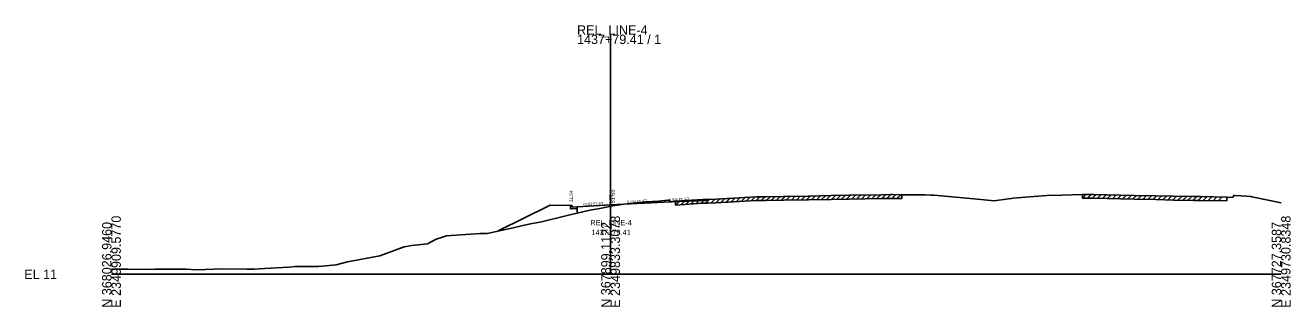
# Model space of a CAD drawing. Extents: x -26 to 2350146, y -10 to 368200.
# Drawn here: x 974.3 to 1351.7, y 9490.3 to 9574.3 of the extents above; entities that cross this region are included whole.
import ezdxf

# ---------------------------------------------------------------- set-up
doc = ezdxf.new("R2010")
doc.units = 0
for name, color, linetype in [('RD_GPK_XS_Cell', 7, 'Continuous'), ('RD_XS_CurbBase', 7, 'Continuous'), ('RD_XS_CurbFront', 7, 'Continuous'), ('RD_XS_CurbTop', 7, 'Continuous'), ('RD_XS_EarthShd', 7, 'Continuous'), ('RD_XS_ExGround', 7, 'Continuous'), ('RD_XS_ExPaveRet', 7, 'Continuous'), ('RD_XS_MatchLine', 7, 'Continuous'), ('RD_XS_Pave', 7, 'Continuous'), ('RD_XS_PaveShd', 7, 'Continuous'), ('RD_XS_TieSlope', 7, 'Continuous'), ('RD_XS_TX_Elev_EX', 7, 'Continuous'), ('RD_XS_TX_Elev_PR', 7, 'Continuous'), ('RD_XS_TX_Slope', 7, 'Continuous'), ('RD_XS_TX_Station', 7, 'Continuous'), ('RD_XS_TX_TOC', 7, 'Continuous')]:
    doc.layers.add(name, color=color, linetype=linetype)

msp = doc.modelspace()

# ---------------------------------------------------------------- linework, layer by layer
at = {"layer": 'RD_GPK_XS_Cell'}
for p, q in [((1148.86, 9500), (1148.86, 9571.52)), ((1000, 9500), (1148.86, 9500)), ((1148.86, 9500), (1348.86, 9500))]:
    msp.add_line(p, q, dxfattribs=at)
at = {"layer": 'RD_XS_CurbBase'}
for p, q in [((1136.86, 9520.54), (1136.86, 9519.54)), ((1136.86, 9519.54), (1137.36, 9519.54)), ((1137.36, 9519.54), (1138.86, 9519.63)), ((1138.86, 9518.56), (1138.86, 9519.63))]:
    msp.add_line(p, q, dxfattribs=at)
at = {"layer": 'RD_XS_CurbFront'}
msp.add_line((1138.86, 9519.63), (1138.86, 9520.13), dxfattribs=at)
at = {"layer": 'RD_XS_CurbTop'}
for p, q in [((1137.36, 9520.54), (1136.86, 9520.54)), ((1137.44, 9520.04), (1137.36, 9520.54)), ((1138.86, 9520.13), (1137.44, 9520.04)), ((1138.86, 9520.15), (1138.86, 9520.13))]:
    msp.add_line(p, q, dxfattribs=at)
at = {"layer": 'RD_XS_EarthShd'}
for p, q in [((1171.88, 9521.82), (1177.88, 9522.06)), ((1136.86, 9520.54), (1130.86, 9520.66))]:
    msp.add_line(p, q, dxfattribs=at)
at = {"layer": 'RD_XS_ExGround'}
msp.add_lwpolyline([(1000, 9501.5), (1001.98, 9501.5), (1002.89, 9501.49), (1004.88, 9501.51), (1012.04, 9501.38), (1013.08, 9501.54), (1019.03, 9501.48), (1022.35, 9501.51), (1025.24, 9501.34), (1030.62, 9501.49), (1033.35, 9501.62), (1040.41, 9501.56), (1041.83, 9501.53), (1042.57, 9501.53), (1044.04, 9501.57), (1049.19, 9501.89), (1053, 9502.11), (1054.76, 9502.29), (1057.27, 9502.31), (1061.75, 9502.36), (1067.05, 9502.85), (1070.35, 9503.69), (1080.07, 9505.46), (1087.28, 9508.18), (1089.56, 9508.63), (1094.22, 9509.08), (1096.82, 9510.48), (1098.73, 9511.04), (1099.9, 9511.47), (1109.98, 9512.19), (1112.01, 9512.18), (1119.76, 9513.88), (1122.31, 9514.5), (1124.5, 9514.91), (1128.24, 9515.68), (1135.49, 9517.43), (1136.28, 9517.61), (1143.21, 9519.21), (1145.11, 9519.57), (1148.53, 9520.23), (1148.86, 9520.28), (1152.83, 9520.91), (1159.51, 9521.6), (1163.2, 9521.86), (1165.96, 9522.09), (1166.48, 9522.1), (1166.66, 9521.61), (1167.13, 9521.64), (1168.27, 9521.77), (1176.3, 9522.33), (1176.74, 9522.35), (1177.55, 9522.39), (1177.83, 9522.32), (1180.24, 9522.43), (1183.61, 9522.61), (1183.94, 9522.66), (1188.82, 9522.94), (1192.23, 9523.15), (1193.4, 9523.16), (1195.19, 9523.13), (1200.41, 9523.24), (1207.85, 9523.34), (1214.69, 9523.47), (1219.99, 9523.58), (1229.64, 9523.75), (1232.49, 9523.8), (1232.99, 9523.79), (1235.77, 9523.75), (1242.7, 9523.67), (1244.39, 9523.61), (1245.4, 9523.59), (1246.48, 9523.53), (1257.17, 9522.54), (1261.28, 9522.11), (1263.31, 9521.94), (1267.54, 9522.51), (1268.4, 9522.63), (1268.82, 9522.67), (1270.14, 9522.79), (1279, 9523.5), (1283.46, 9523.6), (1286.51, 9523.66), (1289.56, 9523.82), (1292.85, 9523.84), (1305.01, 9523.55), (1311.46, 9523.41), (1316.78, 9523.29), (1322.72, 9523.2), (1324.18, 9523.18), (1324.75, 9523.17), (1332.64, 9523.03), (1332.84, 9522.96), (1334.54, 9522.98), (1334.73, 9523.48), (1335.13, 9523.48), (1338.51, 9523.28), (1339.77, 9523.2), (1340.11, 9523.15), (1340.59, 9523.04), (1348.86, 9521.34)], dxfattribs=at)
at = {"layer": 'RD_XS_ExPaveRet'}
for p, q in [((1168.27, 9520.63), (1169.5, 9521.85)), ((1168.27, 9520.63), (1168.27, 9521.77)), ((1169.77, 9520.73), (1171, 9521.96)), ((1171.27, 9520.83), (1172.5, 9522.06)), ((1172.77, 9520.94), (1174, 9522.17)), ((1174.27, 9521.04), (1175.5, 9522.27)), ((1175.77, 9521.15), (1176.98, 9522.36)), ((1177.27, 9521.23), (1178.38, 9522.35)), ((1178.77, 9521.22), (1179.96, 9522.42)), ((1180.27, 9521.29), (1181.48, 9522.5)), ((1181.77, 9521.37), (1182.98, 9522.58)), ((1183.27, 9521.45), (1184.51, 9522.69)), ((1183.94, 9521.52), (1188.82, 9521.8)), ((1184.77, 9521.56), (1185.98, 9522.78)), ((1186.27, 9521.65), (1187.48, 9522.87)), ((1187.77, 9521.74), (1188.98, 9522.95)), ((1188.82, 9521.8), (1192.23, 9522.01)), ((1189.27, 9521.83), (1190.48, 9523.05)), ((1190.77, 9521.92), (1191.98, 9523.14)), ((1192.23, 9522.01), (1193.4, 9522.02)), ((1192.27, 9522.01), (1193.42, 9523.16)), ((1193.4, 9522.02), (1195.19, 9521.99)), ((1193.77, 9522.01), (1194.89, 9523.13)), ((1195.19, 9521.99), (1200.41, 9522.1)), ((1195.27, 9521.99), (1196.43, 9523.16)), ((1196.77, 9522.02), (1197.93, 9523.19)), ((1198.27, 9522.05), (1199.43, 9523.22)), ((1199.77, 9522.08), (1200.93, 9523.25)), ((1200.41, 9522.1), (1207.85, 9522.19)), ((1201.27, 9522.11), (1202.43, 9523.27)), ((1202.77, 9522.13), (1203.93, 9523.29)), ((1204.27, 9522.15), (1205.43, 9523.3)), ((1205.77, 9522.17), (1206.93, 9523.32)), ((1207.27, 9522.19), (1208.43, 9523.35)), ((1207.85, 9522.19), (1214.69, 9522.33)), ((1208.77, 9522.21), (1209.93, 9523.38)), ((1210.27, 9522.24), (1211.43, 9523.41)), ((1211.77, 9522.27), (1212.93, 9523.44)), ((1213.27, 9522.3), (1214.43, 9523.47)), ((1214.69, 9522.33), (1219.99, 9522.44)), ((1214.77, 9522.33), (1215.93, 9523.5)), ((1216.27, 9522.36), (1217.43, 9523.53)), ((1217.77, 9522.39), (1218.93, 9523.56)), ((1219.27, 9522.42), (1220.43, 9523.59)), ((1219.99, 9522.44), (1229.64, 9522.61)), ((1220.77, 9522.45), (1221.93, 9523.61)), ((1222.27, 9522.48), (1223.43, 9523.64)), ((1223.77, 9522.5), (1224.93, 9523.67)), ((1225.27, 9522.53), (1226.43, 9523.7)), ((1226.77, 9522.56), (1227.93, 9523.72)), ((1228.27, 9522.59), (1229.43, 9523.75)), ((1229.64, 9522.61), (1232.49, 9522.66)), ((1229.77, 9522.61), (1230.93, 9523.78)), ((1231.27, 9522.64), (1232.43, 9523.8)), ((1232.49, 9522.66), (1232.99, 9522.65)), ((1232.77, 9522.66), (1233.89, 9523.78)), ((1232.99, 9522.65), (1235.77, 9522.6)), ((1234.27, 9522.63), (1235.39, 9523.75)), ((1235.77, 9523.75), (1235.77, 9522.6)), ((1289.56, 9522.67), (1290.71, 9523.83)), ((1289.56, 9522.67), (1289.56, 9523.82)), ((1289.56, 9522.67), (1292.85, 9522.7)), ((1291.06, 9522.68), (1292.21, 9523.84)), ((1292.56, 9522.7), (1293.69, 9523.82)), ((1292.85, 9522.7), (1305.01, 9522.41)), ((1294.06, 9522.67), (1295.18, 9523.79)), ((1295.56, 9522.63), (1296.68, 9523.75)), ((1297.06, 9522.6), (1298.18, 9523.71)), ((1298.56, 9522.56), (1299.68, 9523.68)), ((1300.06, 9522.53), (1301.18, 9523.64)), ((1301.56, 9522.49), (1302.68, 9523.61)), ((1303.06, 9522.46), (1304.18, 9523.57)), ((1304.56, 9522.42), (1305.68, 9523.54)), ((1305.01, 9522.41), (1311.46, 9522.27)), ((1306.06, 9522.39), (1307.18, 9523.5)), ((1307.56, 9522.35), (1308.68, 9523.47)), ((1309.06, 9522.32), (1310.18, 9523.44)), ((1310.56, 9522.29), (1311.68, 9523.4)), ((1311.46, 9522.27), (1316.78, 9522.15)), ((1312.06, 9522.25), (1313.18, 9523.37)), ((1313.56, 9522.22), (1314.68, 9523.34)), ((1315.06, 9522.18), (1316.18, 9523.3)), ((1316.56, 9522.15), (1317.68, 9523.27)), ((1316.78, 9522.15), (1322.72, 9522.06)), ((1318.06, 9522.13), (1319.19, 9523.25)), ((1319.56, 9522.1), (1320.69, 9523.23)), ((1321.06, 9522.08), (1322.19, 9523.21)), ((1322.56, 9522.06), (1323.69, 9523.18)), ((1322.72, 9522.06), (1324.18, 9522.03)), ((1324.06, 9522.03), (1325.18, 9523.16)), ((1324.18, 9522.03), (1324.75, 9522.02)), ((1324.75, 9522.02), (1332.64, 9521.89)), ((1325.56, 9522.01), (1326.68, 9523.13)), ((1327.06, 9521.98), (1328.18, 9523.11)), ((1328.56, 9521.96), (1329.68, 9523.08)), ((1330.06, 9521.93), (1331.18, 9523.06)), ((1332.64, 9523.03), (1332.64, 9521.89)), ((1168.27, 9520.63), (1176.3, 9521.18)), ((1176.3, 9521.18), (1176.74, 9521.21)), ((1176.74, 9521.21), (1177.55, 9521.25)), ((1177.55, 9521.25), (1177.83, 9521.18)), ((1177.83, 9521.18), (1180.24, 9521.29)), ((1180.24, 9521.29), (1183.61, 9521.47)), ((1183.61, 9521.47), (1183.94, 9521.52))]:
    msp.add_line(p, q, dxfattribs=at)
at = {"layer": 'RD_XS_MatchLine'}
msp.add_line((1177.88, 9522.06), (1177.88, 9522.32), dxfattribs=at)
at = {"layer": 'RD_XS_Pave'}
for p in [(1138.86, 9520.15), (1164.86, 9521.54)]:
    msp.add_line(p, (1148.86, 9520.68), dxfattribs=at)
at = {"layer": 'RD_XS_PaveShd'}
msp.add_line((1171.88, 9521.82), (1164.86, 9521.54), dxfattribs=at)
at = {"layer": 'RD_XS_TieSlope'}
msp.add_line((1130.86, 9520.66), (1115.37, 9512.92), dxfattribs=at)

# ---------------------------------------------------------------- texts
at = {"layer": 'RD_GPK_XS_Cell'}
for s, p in [('1437+79.41 / 1', (1138.86, 9568.72)), ('REL_LINE-4', (1138.86, 9571.52)), ('EL 11', (974, 9498.6))]:
    msp.add_text(s, height=2.8, dxfattribs=at).set_placement(p)
for s, p in [('N 368026.9460', (1000, 9490)), ('E 2349909.5770', (1002.8, 9490)), ('N 367899.1122', (1148.86, 9490)), ('E 2349833.3078', (1151.66, 9490)), ('N 367727.3587', (1348.86, 9490)), ('E 2349730.8348', (1351.66, 9490))]:
    msp.add_text(s, height=2.8, rotation=90, dxfattribs=at).set_placement(p)
at = {"layer": 'RD_XS_TX_Elev_EX'}
msp.add_text('31.28', height=1, rotation=90, dxfattribs=at).set_placement((1149.36, 9520.28))
at = {"layer": 'RD_XS_TX_Elev_PR'}
for s, height, p in [('31.54', 1, (1137.61, 9521.54)), (' 31.68', 1.2, (1150.06, 9520.68))]:
    msp.add_text(s, height=height, rotation=90, dxfattribs=at).set_placement(p)
at = {"layer": 'RD_XS_TX_Slope'}
for s, rotation, p in [('0.053 FT./FT.', 3.0619, (1140.82, 9520.5)), ('0.054 FT./FT.', 3.0629, (1153.82, 9521.2)), ('0.040 FT./FT.', 2.3025, (1166.33, 9521.85))]:
    msp.add_text(s, height=0.75, rotation=rotation, dxfattribs=at).set_placement(p)
at = {"layer": 'RD_XS_TX_Station'}
for s, p in [('REL_LINE-4', (1142.79, 9514.58)), ('1437+79.41', (1143.16, 9511.68))]:
    msp.add_text(s, height=1.6, dxfattribs=at).set_placement(p)
at = {"layer": 'RD_XS_TX_TOC'}
msp.add_text('TOCLT', height=0.05, dxfattribs=at).set_placement((1137.41, 9520.49))

doc.saveas('drawing.dxf')
